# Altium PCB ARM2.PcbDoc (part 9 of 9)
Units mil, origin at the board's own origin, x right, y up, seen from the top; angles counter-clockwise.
Board outline 4700.79 x 3937.01 mil, 6 copper layers (Top Layer, GND02, ART03, ART04, PWR05, Bottom Layer); 697 components, 508 nets, 2326 pads, 1231 vias.
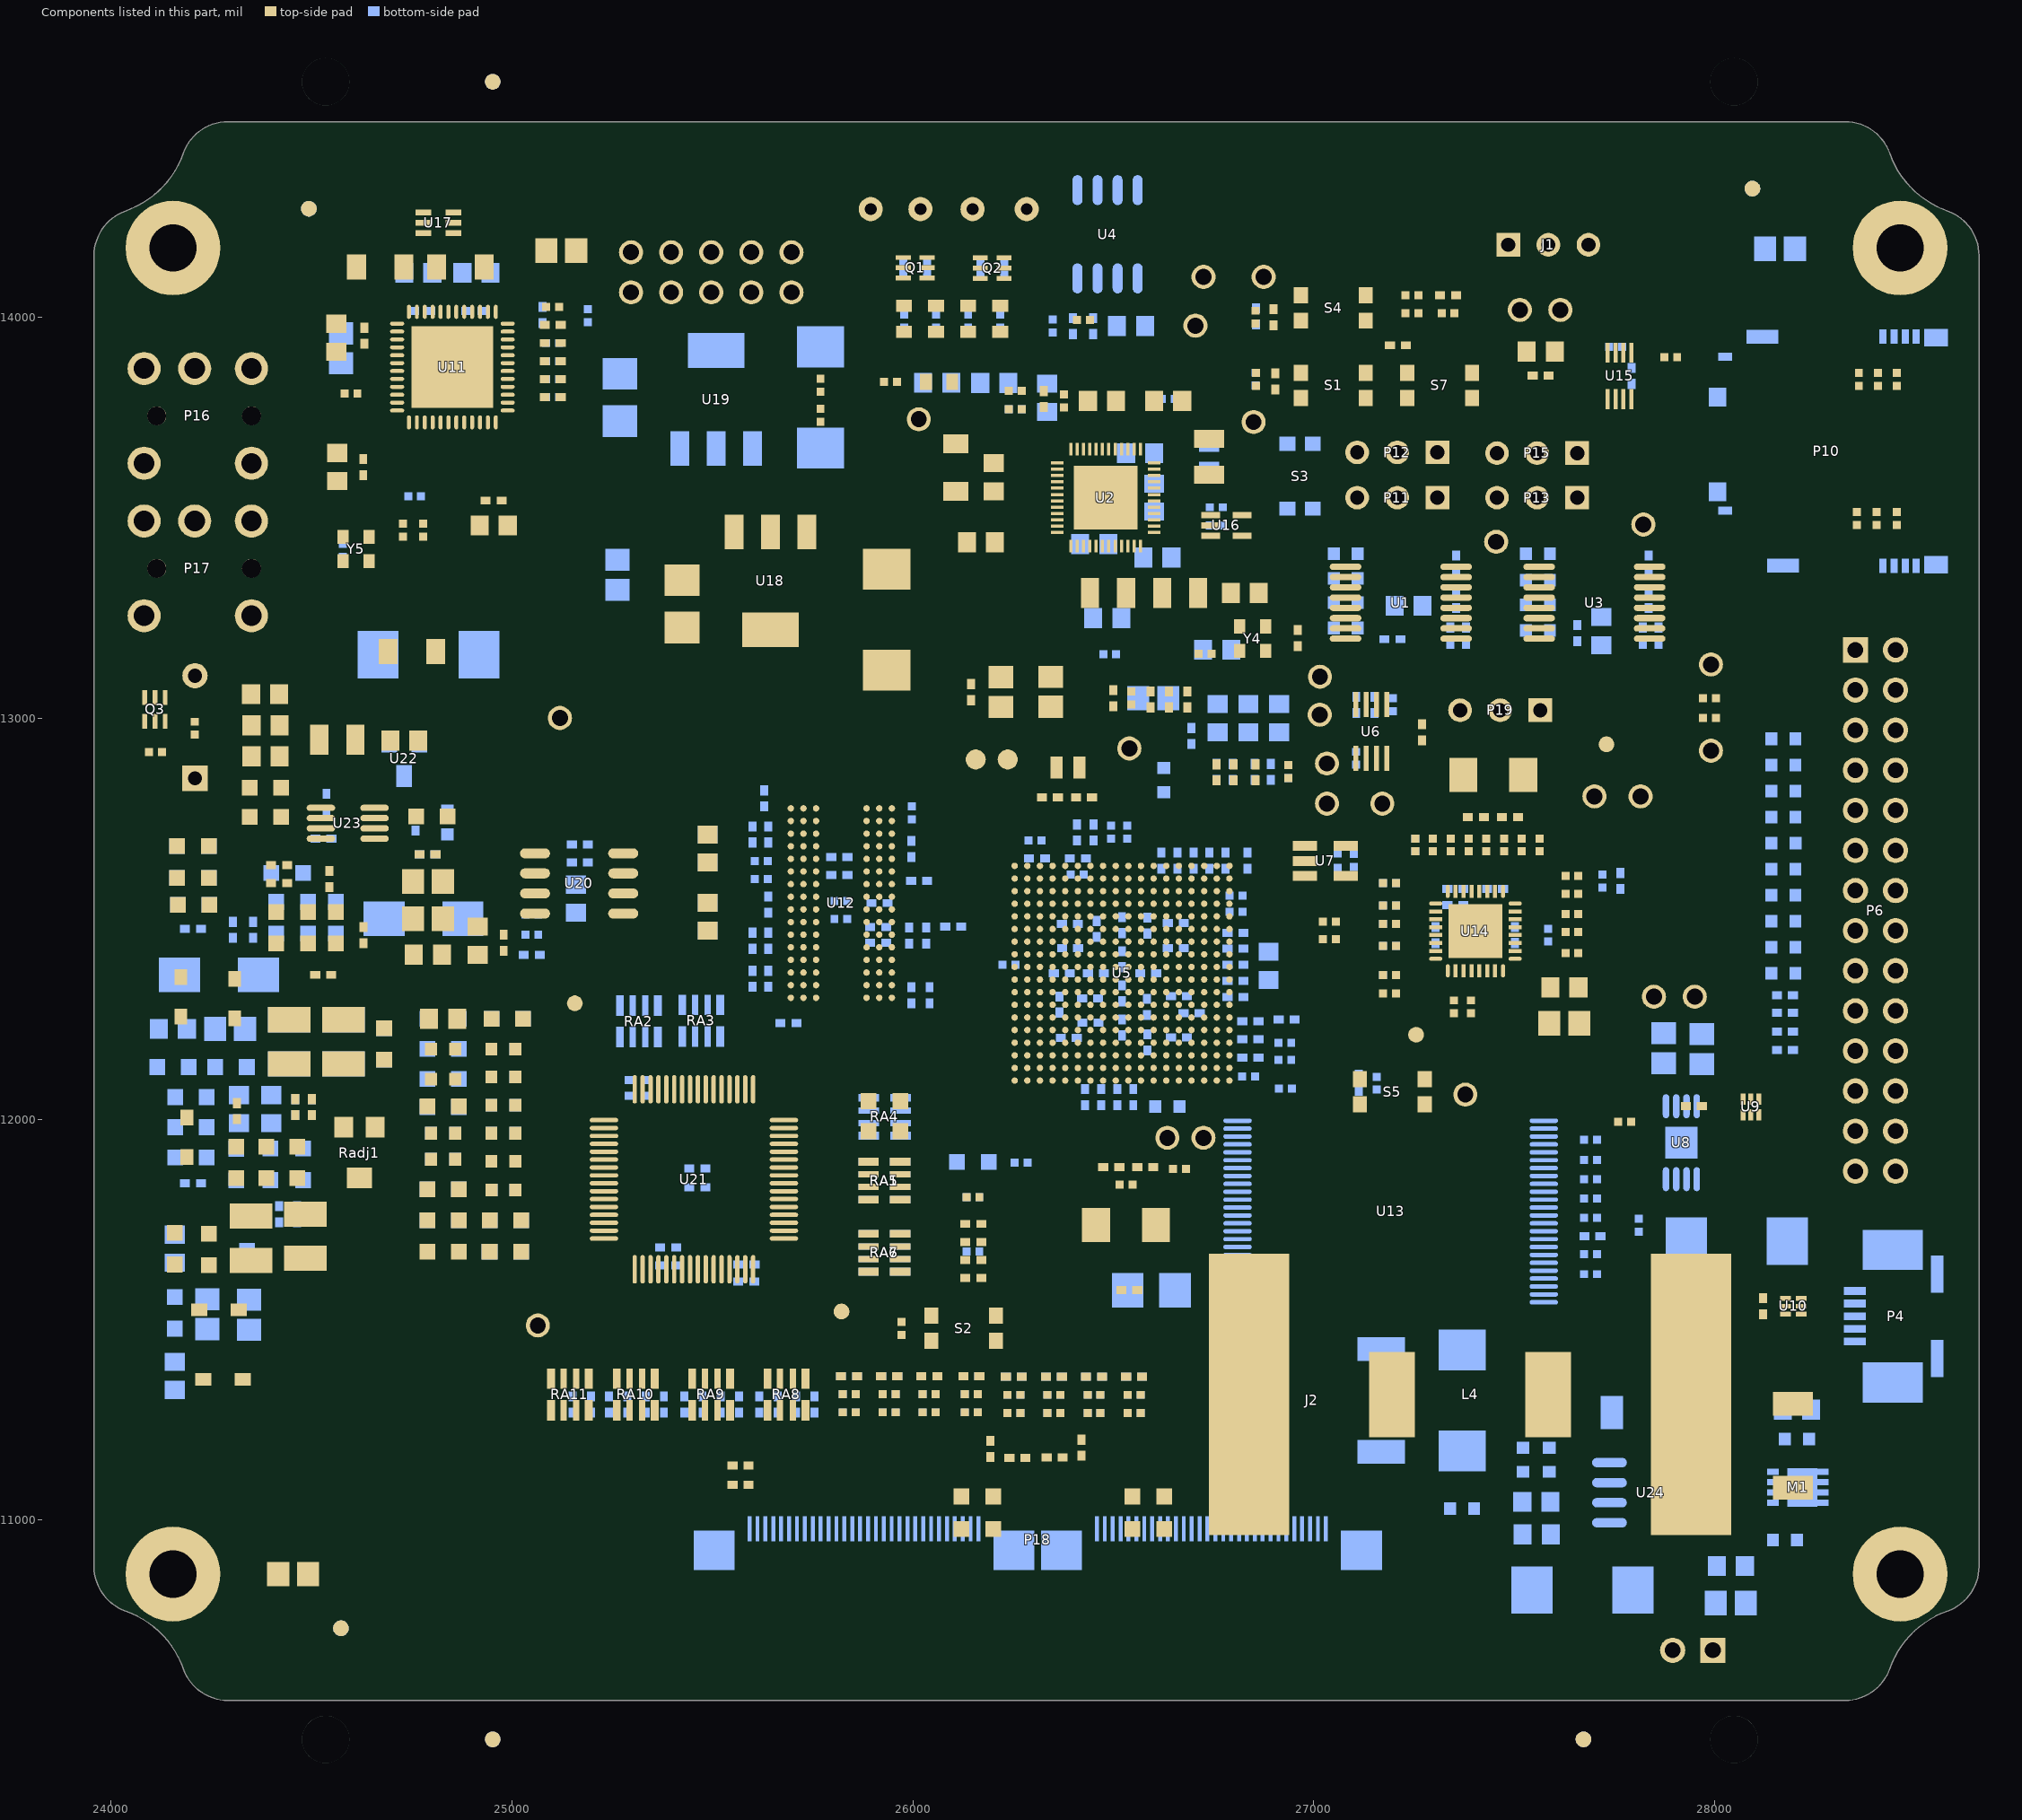
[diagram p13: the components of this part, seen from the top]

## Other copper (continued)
PWR05 (plane layer: these items are gaps in the copper):
  circle w80: c24351,13373.62 r12
  circle w80: c24114.78,13373.62 r12
  circle w80: c24351,13753.89 r12
  circle w80: c24114.78,13753.89 r12
  pour cut-out: 23975.92,10845.92 cw(c23983,10853) 23972.99,10853 23972.99,11087.56 23957.93,11087.56 cw(c23957.93,11107.57) 23957.93,11127.59 24314.12,11127.59 cw(c24314.12,11107.57) 24328.31,11121.69 24328.28,11121.73 24407.28,11042.73 24407.24,11042.76 cw(c24393.12,11028.57) 24413.14,11028.57 24413.14,10686.86 24448.42,10651.59 28228.83,10651.59 28259.11,10681.86 28259.11,10926.57 cw(c28279.12,10926.57) 28265.01,10940.76 28264.97,10940.73 28391.11,11066.86 28391.11,11756.57 cw(c28411.12,11756.57) 28397.01,11770.76 28396.97,11770.73 28488.11,11861.86 28488.11,13890.28 28429.83,13948.56 28307.12,13948.56 cw(c28307.12,13968.57) 28292.94,13954.46 28292.97,13954.42 28236.97,14010.42 28237.01,14010.39 cw(c28251.12,14024.57) 28231.11,14024.57 28231.11,14306.28 28156.83,14380.56 24441.42,14380.56 24395.14,14334.28 24395.14,14020.57 cw(c24375.12,14020.57) 24389.24,14006.39 24389.28,14006.42 24338.28,13955.42 24338.31,13955.46 cw(c24324.12,13969.57) 24324.12,13949.56 23973.12,13949.56 cw(c23973.12,13969.57) 23967.99,13988.92 23967.99,14176 cw(c23978,14176) 23970.92,14183.08 24260.92,14473.08 cw(c24268,14466) 24268,14476.01 28347,14476.01 cw(c28347,14466) 28354.08,14473.08 28649.08,14178.08 cw(c28642,14171) 28652.01,14171 28652.01,10872 cw(c28642,10872) 28649.08,10864.92 28337.08,10552.92 cw(c28330,10560) 28330,10549.99 24276,10549.99 cw(c24276,10560) 24268.92,10552.92
  lines w15: 24447.12,13325.89 25138.05,13325.89 25200.89,13388.73 25200.89,13540.28 25243.4,13582.79 25583.48,13582.79 25639,13527.27 25639,13000.66 ; 25254.12,12737.57 24685.12,12737.57 24655,12707.45 24655,11855 24726,11784 24816,11694 24816,11033.8 24844.8,11005 27082.45,11005 27112.06,11034.61 27112.06,12598.77 27112.06,12624.58 27242.12,12754.64 27242.12,14005.34 ; 25738,11005 25738,12059.88 ; 25898.75,14406.7 25898.75,13800.19 26028.48,13670.46 26028.48,13309.31 ; 26378.4,12225 26623.55,12225 26632.12,12233.57 26632.12,12473.57 26632.12,12534.65 26632.12,12658.57 26958.12,12984.57 26958.12,13647.57 26940.12,13665.57 26677.7,13665.57 ; 26677.7,13320.72 26677.7,13736.17 26655.29,13758.57 26352.12,13758.57 26324.12,13786.57 26324.12,13978.46 26351.01,14005.34 27140.24,14005.34 27241.94,14005.34 27241.94,14030.33 27280.99,14069.39 27816.29,14069.39 27863.06,14022.61 27863.06,11567.57 27112.06,11567.57 ; 26678.17,13318.57 26029.5,13318.57 26028.48,13317.55 26028.48,13106.19 25921.16,12998.88 25511.43,12998.88 25338.12,12825.57 25254.12,12741.57 25254.12,12089.57 25283.82,12059.88 26349.43,12059.88 26378.4,12088.85 26378.4,12352.76 26378.4,12871.85 26678.17,13171.62 26678.17,13320.25 ; 27840.12,11567.57 28410.12,11567.57 ; 28656.85,13041.85 28656.85,13185
  lines w20: 23978,13969.57 23978,14176 24268,14466 28347,14466 28642,14171 28642,10872 28330,10560 24276,10560 23983,10853 23983,11107.57
  lines w40: 23957.93,11107.57 24314.12,11107.57 24393.12,11028.57 24393.12,10678.57 24440.12,10631.57 28237.12,10631.57 28279.12,10673.57 28279.12,10926.57 28411.12,11058.57 28411.12,11756.57 28508.12,11853.57 28508.12,13898.57 28438.12,13968.57 28307.12,13968.57 28251.12,14024.57 28251.12,14314.57 28165.12,14400.57 24433.12,14400.57 24375.12,14342.57 24375.12,14020.57 24324.12,13969.57 23973.12,13969.57 ; 23960.98,13169.57 24400.12,13169.57 24447.12,13216.57 24447.12,13708.59 24468.11,13729.57 25099.12,13729.57 25124.12,13754.57 25124.12,14400.57
  text "PWR05" at 25812,14809 h100

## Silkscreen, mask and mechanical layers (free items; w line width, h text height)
Top Overlay:
  circle w5: c26352,11966 r32.61
  lines w5: 24122,11892 24122,11747.87 24269,11747.87 24269,11821.13 24281.5,11821.13 ; 24236,12138.64 24236,11970.34 24530,11970.34 24530,12081.09 24378.17,12081.09 ; 24451,12870 24466,12870 24471,12865 24471,12848 24482,12837 24606,12837 ; 27328,12648.17 27328,12635 27882,12635 27882,12710 ; 27529.3,12761 27531.3,12759 27578,12759 27593,12774 27649,12774 27650,12775 27650,12897 ; 25675,11033 26084,11033 26084,11134 26104,11134 26118,11134 26118,11176 26118,11237 26194,11237 26194,11406 25780,11406 25780,11195 25732,11195 25675,11195 25675,11033 ; 26205,11232 26720,11232 26720,11543 26681,11543 26245,11543 26245,11396 26205,11396 26205,11367.09 26205,11232 ; 26865,12135 27030,12135 27030,12275 27245,12275 27245,12620 27140,12620 27140,12410 26865,12410 26865,12135
  text "ZFCS" at 25356.66,12939.69 h100
  text "eMMC_RSTn" at 26260,12014 h25
Bottom Overlay:
  lines w4: 26825,12810 26860.81,12810 26860.81,12716.08 26992.99,12716.08 26992.99,12920 26825,12920 26825,12810
  lines w5: 24134.13,12570.5 24021,12570.5 24021,12733 24276.22,12733 24276.22,12712.24 ; 24381.32,12573.24 24525,12573.24 24525,12664 24576,12664 24576,12714 24714,12714 24714,12699 24714,12577 24592.5,12577 24592.5,12568 ; 25585,12504 25622,12504 ; 26321.06,11884 26365,11884 26365,11935 26321.06,11935 ; 26630,12540 26630,12590 26690,12590 26690,12540 ; 26208.06,11635.61 26336.11,11635.61 26395.06,11635.61 26689.24,11635.61 26689.24,11826.61 26593.06,11826.61 26593.06,11999.61 26321.06,11999.61 26321.06,11855.61 26208.06,11855.61 26208.06,11635.61 ; 26315,12170 26480,12170 26480,12130 26630,12130 26630,12180.61 26750,12180.61 26750,12350 26710,12350 26710,12540 26490,12540 26490,12400 26330,12400 26315,12400 26315,12170
  text "A" at 26670,12550 h30
  text "A" at 26348,11896 h30
Mechanical 1:
  lines w5: 25438.35,10638.25 25438.35,10719.25 27178.5,10719.25 27178.5,10638.25 25438.35,10638.25
  lines w10: 24292.34,10550.61 cw(c24292.34,10668.72) 24180.99,10629.35 ccw(c23958.27,10550.61) 24037.01,10773.32 cw(c24076.39,10884.68) 23958.27,10884.68 23958.27,14153.56 cw(c24076.38,14153.56) 24037.01,14264.91 ccw(c23958.27,14487.62) 24180.99,14408.88 cw(c24292.34,14369.51) 24292.34,14487.62 ; 24292.34,10550.61 23958,10550.61 23958,10432.5 ccw(c24036.74,10432.5) 24036.74,10353.76 28580.32,10353.76 ccw(c28580.32,10432.5) 28659.06,10432.5 28659.06,10550.61 28325,10550.61 ; 24292.34,10550.61 28325,10550.61 ; 24292.34,14487.62 28325,14487.62 ; 24292.34,14487.62 23958.28,14487.62 23958.28,14605.73 cw(c24037.02,14605.73) 24037.02,14684.47 28580.6,14684.47 cw(c28580.6,14605.73) 28659.34,14605.73 28659.34,14487.62 28325,14487.62 ; 28325,10550.61 ccw(c28325,10668.72) 28436.35,10629.35 cw(c28659.06,10550.62) 28580.32,10773.32 ccw(c28540.95,10884.68) 28659.06,10884.68 28659.06,14153.56 ccw(c28540.95,14153.56) 28580.32,14264.91 cw(c28659.06,14487.62) 28436.35,14408.88 ccw(c28325,14369.52) 28325,14487.62
  text "此处开槽" at 26262,10656 h50
Mechanical 5:
  circle w5: c28462.21,14172.66 r59.06
  circle w5: c24155.12,14172.66 r59.06
  circle w5: c24155.12,10865.57 r59.06
  circle w5: c28462.21,10865.57 r59.06
Drill Drawing:
  drawing of 9402 lines, arcs and shapes, not listed
  text "Purchase   Order &  Specification   Sheet" at 33244.42,19132.41 h30
  text "Dielectric Material:" at 32355.32,19006.78 h30
  text "S1141" at 33356.2,19002.84 h30
  text "Board Thickness(MM):" at 33854.14,19003.23 h30
  text "1.6+/-0.25" at 34706.23,19002.88 h30
  text "Layers:" at 35234.45,19003.23 h30
  text "6" at 35807.61,19002.84 h30
  text "Hasl" at 33356.11,18802.84 h30
  text "Osp" at 36150.6,18802.84 h30
  text "Gold Finger" at 35424.73,18800.52 h30
  text "Surface Finished:" at 32356.89,18799.69 h30
  text "Flash Gold" at 34028.94,18799.69 h30
  text "Immersion Gold" at 34649.02,18796.54 h30
  text "Hasl Lead Free" at 33346.66,18659.14 h30
  text "Immersion Tin" at 34025.79,18652.84 h30
  text "Immersion Silver" at 34650.6,18651.27 h30
  text "Other" at 35428.15,18650.08 h30
  text "Angle" at 33716.07,18509.18 h30
  text "Yes" at 33350.53,18508.04 h30
  text "30" at 34658.2,18507.61 h30
  text "45" at 35435.36,18508 h30
  text "No" at 36150.72,18506.82 h30
  text "20" at 34023.95,18503.67 h30
  text "Finger Chamfer:" at 32359.32,18499.04 h30
  text "Matte Green" at 34639.97,18357.96 h30
  text "Other" at 35425.4,18353.63 h30
  text "Blue" at 34030.91,18352.84 h30
  text "Green" at 33350.99,18350.87 h30
  text "Soldermask Colours:" at 32356.5,18346.15 h30
  text "Black" at 34642.33,18208.35 h30
  text "Other" at 35429.34,18207.56 h30
  text "Silk Screen Colours:" at 32354.14,18202.45 h30
  text "White" at 33350.99,18202.05 h30
  text "Yellow" at 34027.76,18197.72 h30
  text "Spell Mode:" at 32348.63,18018.59 h30
  text "Open Windows:" at 34534.06,18016.62 h30
  text "None" at 35074.61,18015.05 h30
  text "V-cut" at 35058.47,17859.53 h30
  text "Bridge" at 34024.73,17858.39 h30
  text "Stamp Hole" at 36030.12,17857.56 h30
  text "Outline Profile:" at 32352.17,17852.05 h30
  text "Router" at 33354.14,17848.12 h30
  text "Gjb362B" at 35057.29,17711.9 h30
  text "QJ831B" at 36032.88,17711.11 h30
  text "IPCII" at 33361.62,17709.53 h30
  text "IPCIII" at 34023.16,17708.39 h30
  text "Inspectionstandard:" at 32349.02,17707.17 h30
  text "No" at 34027.49,17563.51 h30
  text "Yes" at 33361.62,17558.35 h30
  text "Compare With IPC File:" at 32349.41,17550.87 h30
  text "Not Appear" at 36028.15,17409.93 h30
  text "Specified Position" at 34022.37,17408.39 h30
  text "Required" at 33357.68,17401.66 h30
  text "Only Date Code" at 35062.41,17402.05 h30
  text "Fast Print Logo:" at 32352.96,17398.12 h30
  text "All via (<=0.5mm) must be filled(except open soldermask via)" at 33359.38,17255.64 h30
  text "By gerber" at 36023.04,17250.48 h30
  text "Via  Technic:" at 32347.84,17241.42 h30
  text "4.3mil" at 32943,17098 h20
  text "8mil" at 34768,17096 h20
  text "(unit:mil)MIN.track :                       MIN.spacing :                 MIN.hole:" at 32351.5,17093.83 h30
  text "4.3mil" at 34000,17093 h20
  text "Pressfit holes: The tolerance of                 is+/-0.05mm" at 33606.5,16948.12 h30
  text "Bow and Twist Tolerance:<=0.75%" at 32348.63,16944.18 h30
  text "1.  STACKING (dielectric thickness can be adjusted beween +/-2mil,but don,t less than 3.5mil;" at 32446.39,16696.58 h30
  text "IF inspection is Gjb362A or QJ831B then don,t less than 4mil.)" at 32446.39,16596.58 h30
  text "2.  Control Impedance (track width can be adjusted +/-0.5mil , but don,t less than 4mil.)" at 32446.39,16496.58 h30
  text "TOP" at 36086.72,14487.35 h30
  text "0.33oz+Plating" at 35441.27,14450.12 h30
  text "3.90mil" at 32578.67,14346.58 h30
  text "PP3313" at 33468.04,14341.07 h30
  text "GND02" at 36086.72,14267.35 h30
  text "0.5oz" at 35750.72,14239.1 h30
  text "3.94mil" at 32578.67,14126.9 h30
  text "CORE" at 33468.43,14122.17 h30
  text "ART03" at 36086.72,14047.35 h30
  text "0.5oz" at 35750.72,14019.41 h30
  text "39.91mil" at 32578.67,13907.21 h30
  text "PP2116+CORE(31.49)+2116" at 33786.15,13898.15 h30
  text "ART04" at 36086.72,13827.35 h30
  text "0.5oz" at 35750.72,13799.73 h30
  text "3.94mil" at 32578.67,13687.52 h30
  text "CORE" at 33468.43,13682.8 h30
  text "PWR05" at 36086.72,13607.35 h30
  text "0.5oz" at 35750.72,13580.04 h30
  text "3.90mil" at 32578.67,13467.84 h30
  text "PP3313" at 33468.04,13462.33 h30
  text "BOTTOM" at 36086.72,13387.35 h30
  text "0.33oz+Plating" at 35485.17,13339.89 h30
  text "ref layer" at 35294.4,10801.04 h30
  text "*" at 36011.74,10685.95 h30
  text "L1/L6" at 32823.55,10682.4 h30
  text "6.0" at 33273.55,10682.01 h30
  text "50" at 33923.55,10682.01 h30
  text "+/-10%" at 34623.55,10682.01 h30
  text "L2;L5" at 35223.55,10682.4 h30
  text "L3/L4" at 32823.55,10570.59 h30
  text "L2/L5" at 35223.55,10570.59 h30
  text "5.5" at 33273.55,10570.2 h30
  text "50" at 33923.55,10570.2 h30
  text "+/-10%" at 34623.55,10570.2 h30
  text "ref layer" at 35316.77,8714.02 h30
  text "*" at 36011.74,8598.94 h30
  text "L1/L6" at 32823.55,8593.03 h30
  text "4.4/7.5" at 33323.55,8593.03 h30
  text "100" at 33923.55,8593.03 h30
  text "+/-10%" at 34623.55,8593.03 h30
  text "L2;L5" at 35223.55,8593.03 h30
  text "L1/L6" at 32823.55,8483.19 h30
  text "5.5/7.0" at 33323.55,8483.19 h30
  text "90" at 33923.55,8483.19 h30
  text "+/-10%" at 34623.55,8483.19 h30
  text "L2;L5" at 35223.55,8483.19 h30
  text "L4/L3" at 32823.16,8373.35 h30
  text "4.3/8.0" at 33323.16,8373.35 h30
  text "100" at 33923.16,8373.35 h30
  text "+/-10%" at 34623.16,8373.35 h30
  text "L2/L5" at 35223.16,8373.35 h30
  text "L4" at 32863.01,8266.32 h30
  text "5.5/8.0" at 33323.55,8263.11 h30
  text "90" at 33923.55,8263.11 h30
  text "+/-10%" at 34623.55,8263.11 h30
  text "L2/L5" at 35223.55,8263.11 h30
  text "Note:If etch layer don't have  above impedance track pls ignore" at 32376.31,7341.85 h30
  text "armv2" at 34644.81,6811.54 h30
  text "Board Name:" at 32226.18,6805.98 h30
  text "A" at 37641.15,6787.09 h30
  text "REV:" at 37006.5,6775.67 h30
  text "Fastprint PN:" at 32231.82,6382.01 h30
  text "K01BC006A0" at 34627.49,6382.4 h30
  text "Lead Time:" at 32239.3,5972.17 h30
  text "2014-06-16" at 34622.76,5918.23 h30
  text "Technical Questions Contact:" at 29117.64,5842.24 h30
  text "To: JLP@chinafastprint.com                   cc:xhj@chinafastprint.com" at 29601.5,5632.01 h30
  text "Email" at 29106.8,5614.64 h30
  text "Tel: 0755-26508455   Fax:    Mobile:13632789305" at 29597.84,5406.38 h30
  text "TEL" at 29112.4,5402.83 h30

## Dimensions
23958,10550.61 to 24292.34,14487.62 on Drill Drawing
23958.27,10884.68 to 28659.06,10884.68 on Drill Drawing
